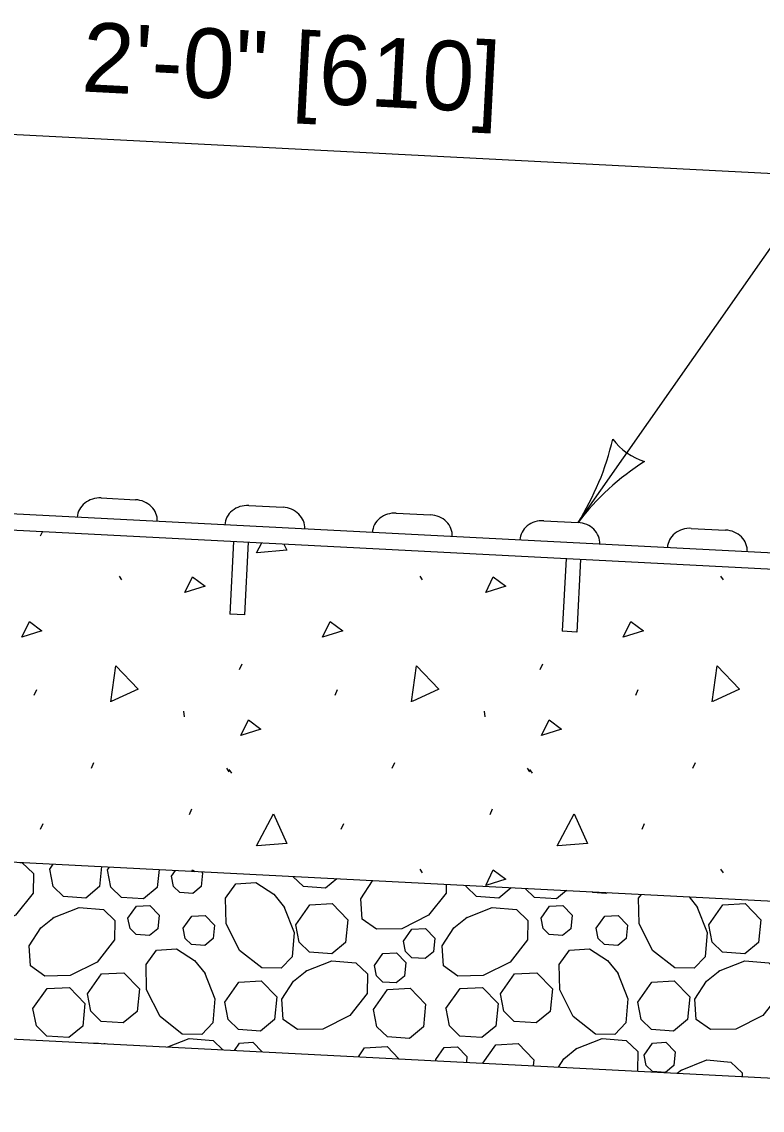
# Model space of a CAD drawing. Extents: x 49991.4 to 50021, y 49987.6 to 50011.4.
# Drawn here: x 50004.422 to 50005.061, y 50003.543 to 50004.482 of the extents above; entities that cross this region are included whole.
import ezdxf

# ---------------------------------------------------------------- set-up
doc = ezdxf.new("R2010")
doc.units = 0
for name, color, linetype in [('Level 1', 7, 'Continuous'), ('Level 2', 7, 'Continuous'), ('Level 3', 7, 'Continuous')]:
    doc.layers.add(name, color=color, linetype=linetype)

msp = doc.modelspace()

# ---------------------------------------------------------------- linework, layer by layer
at = {"layer": 'Level 1'}
for p, q in [((50005.6078, 50003.99629), (50003.78023, 50004.09047)), ((50005.60708, 50003.98226), (50003.7795, 50004.07644)), ((50004.49059, 50004.07152), (50004.52017, 50004.06999)), ((50004.6178, 50004.06496), (50004.64738, 50004.06344)), ((50004.74501, 50004.0584), (50004.77459, 50004.05688)), ((50004.87222, 50004.05185), (50004.9018, 50004.05032)), ((50004.99943, 50004.04529), (50005.02901, 50004.04377)), ((50004.60469, 50004.03391), (50004.60146, 50003.97124)), ((50004.61728, 50004.03326), (50004.61405, 50003.97059)), ((50004.89144, 50004.01914), (50004.88821, 50003.95646)), ((50004.90402, 50004.01849), (50004.90079, 50003.95581)), ((50004.61405, 50003.97059), (50004.60146, 50003.97124)), ((50004.90079, 50003.95581), (50004.88821, 50003.95646)), ((50002.75553, 50003.84288), (50005.60777, 50003.69589)), ((50002.72051, 50003.69208), (50005.60777, 50003.54329))]:
    msp.add_line(p, q, dxfattribs=at)
msp.add_lwpolyline([(50004.48395, 50003.6012), (50004.48808, 50003.60123), (50004.4883, 50003.60098)], dxfattribs=at)
for centre, major_axis, start_param, end_param in [((50004.48967, 50004.05391), (0.01967, -0.00101), 1.570424, 3.141593), ((50004.51927, 50004.05238), (-0.01967, 0.00101), 3.141593, 4.712762), ((50004.61688, 50004.04735), (0.01967, -0.00101), 1.570424, 3.141593), ((50004.64648, 50004.04583), (-0.01967, 0.00101), 3.141593, 4.712762), ((50004.74409, 50004.0408), (0.01967, -0.00101), 1.570424, 3.141593), ((50004.77369, 50004.03927), (-0.01967, 0.00101), 3.141593, 4.712762), ((50004.87131, 50004.03424), (0.01967, -0.00101), 1.570424, 3.141593), ((50004.9009, 50004.03272), (-0.01967, 0.00101), 3.141593, 4.712762), ((50004.99852, 50004.02769), (0.01967, -0.00101), 1.570424, 3.141593), ((50005.02811, 50004.02616), (-0.01967, 0.00101), 3.141593, 4.712762)]:
    msp.add_ellipse(centre, major_axis=major_axis, ratio=0.895257, start_param=start_param, end_param=end_param, dxfattribs=at)
at = {"layer": 'Level 2'}
for p, q in [((50004.43834, 50004.03878), (50004.43995, 50004.0424)), ((50004.62458, 50004.02417), (50004.62907, 50004.03266)), ((50004.50601, 50004.00414), (50004.50818, 50004.00089)), ((50004.76532, 50004.00414), (50004.76749, 50004.00089)), ((50005.02463, 50004.00414), (50005.0268, 50004.00089)), ((50004.60996, 50003.92348), (50004.61212, 50003.92835)), ((50004.86927, 50003.92348), (50004.87143, 50003.92835)), ((50004.43293, 50003.90128), (50004.4351, 50003.90616)), ((50004.69224, 50003.90128), (50004.69441, 50003.90616)), ((50004.95155, 50003.90128), (50004.95372, 50003.90616)), ((50004.56163, 50003.88769), (50004.56218, 50003.88282)), ((50004.82094, 50003.88769), (50004.82149, 50003.88282)), ((50004.48219, 50003.83849), (50004.48436, 50003.84336)), ((50004.7415, 50003.83849), (50004.74367, 50003.84336)), ((50005.00081, 50003.83849), (50005.00298, 50003.84336)), ((50004.59858, 50003.83849), (50004.60075, 50003.83524)), ((50004.60075, 50003.83726), (50004.60292, 50003.83401)), ((50004.85789, 50003.83849), (50004.86006, 50003.83524)), ((50004.86006, 50003.83726), (50004.86223, 50003.83401)), ((50004.56664, 50003.79836), (50004.56881, 50003.80323)), ((50004.82595, 50003.79836), (50004.82812, 50003.80323)), ((50004.43834, 50003.78591), (50004.44051, 50003.79078)), ((50004.69765, 50003.78591), (50004.69982, 50003.79078)), ((50004.95696, 50003.78591), (50004.95913, 50003.79078)), ((50004.44631, 50003.75132), (50004.44931, 50003.75559)), ((50004.49609, 50003.75058), (50004.49785, 50003.75309)), ((50004.55115, 50003.74527), (50004.55459, 50003.75017)), ((50004.76532, 50003.75127), (50004.76749, 50003.74802)), ((50005.02463, 50003.75127), (50005.0268, 50003.74802)), ((50004.9976, 50003.72734), (50005.00487, 50003.71823)), ((50004.77926, 50003.58599), (50004.77907, 50003.58694)), ((50004.9873, 50003.57526), (50004.99103, 50003.57824))]:
    msp.add_line(p, q, dxfattribs=at)
for points in [[(50004.64817, 50004.03167), (50004.65056, 50004.02633), (50004.62512, 50004.02417)], [(50004.56285, 50003.99006), (50004.56935, 50004.0036), (50004.58017, 50003.99548), (50004.56285, 50003.99006)], [(50004.82216, 50003.99006), (50004.82866, 50004.0036), (50004.83948, 50003.99548), (50004.82216, 50003.99006)], [(50004.42221, 50003.95137), (50004.42871, 50003.9649), (50004.43953, 50003.95678), (50004.42221, 50003.95137)], [(50004.68152, 50003.95137), (50004.68802, 50003.9649), (50004.69884, 50003.95678), (50004.68152, 50003.95137)], [(50004.94083, 50003.95137), (50004.94733, 50003.9649), (50004.95815, 50003.95678), (50004.94083, 50003.95137)], [(50004.49879, 50003.89568), (50004.50308, 50003.92662), (50004.52247, 50003.9066), (50004.4993, 50003.89587)], [(50004.7581, 50003.89568), (50004.76239, 50003.92662), (50004.78178, 50003.9066), (50004.75861, 50003.89587)], [(50005.01741, 50003.89568), (50005.0217, 50003.92662), (50005.04109, 50003.9066), (50005.01792, 50003.89587)], [(50004.61104, 50003.86664), (50004.61754, 50003.88017), (50004.62836, 50003.87205), (50004.61104, 50003.86664)], [(50004.87035, 50003.86664), (50004.87685, 50003.88017), (50004.88767, 50003.87205), (50004.87035, 50003.86664)], [(50004.62458, 50003.7713), (50004.63919, 50003.7989), (50004.65056, 50003.77346), (50004.62512, 50003.7713)], [(50004.88389, 50003.7713), (50004.8985, 50003.7989), (50004.90987, 50003.77346), (50004.88443, 50003.7713)], [(50004.42033, 50003.75708), (50004.42224, 50003.75692), (50004.43212, 50003.74752), (50004.43181, 50003.73065), (50004.41681, 50003.71148), (50004.39362, 50003.69989), (50004.37178, 50003.6995), (50004.35948, 50003.70824), (50004.35831, 50003.72564), (50004.3683, 50003.7412), (50004.37972, 50003.75032)], [(50004.49093, 50003.75345), (50004.48921, 50003.7362), (50004.47728, 50003.72627), (50004.45821, 50003.72765), (50004.44923, 50003.73635), (50004.44632, 50003.75131)], [(50004.54054, 50003.75089), (50004.539, 50003.73546), (50004.52706, 50003.72554), (50004.50798, 50003.72692), (50004.49901, 50003.73562), (50004.4961, 50003.75058)], [(50004.57699, 50003.74901), (50004.57806, 50003.7479), (50004.57689, 50003.7362), (50004.56973, 50003.73024), (50004.55829, 50003.73107), (50004.55289, 50003.73629), (50004.55115, 50003.74526)], [(50004.56873, 50003.74944), (50004.56935, 50003.75073), (50004.57124, 50003.74931)], [(50004.82216, 50003.73719), (50004.82866, 50003.75073), (50004.83948, 50003.74261), (50004.82216, 50003.73719)], [(50004.64811, 50003.71915), (50004.6571, 50003.69651), (50004.6553, 50003.67571), (50004.6459, 50003.66583), (50004.62903, 50003.66614), (50004.60985, 50003.68115), (50004.59826, 50003.70432), (50004.59788, 50003.72617), (50004.60662, 50003.73847), (50004.62402, 50003.73964), (50004.63958, 50003.72966), (50004.6487, 50003.71823)], [(50004.69385, 50003.74299), (50004.684, 50003.7348), (50004.66492, 50003.73618), (50004.65594, 50003.74489), (50004.65593, 50003.74494)], [(50004.78811, 50003.73813), (50004.78797, 50003.73065), (50004.77297, 50003.71148), (50004.74979, 50003.69989), (50004.72794, 50003.6995), (50004.71564, 50003.70824), (50004.71448, 50003.72564), (50004.72446, 50003.7412), (50004.7247, 50003.7414)], [(50004.84422, 50003.73524), (50004.83344, 50003.72627), (50004.81437, 50003.72765), (50004.8054, 50003.73635), (50004.80522, 50003.73725)], [(50004.89194, 50003.73278), (50004.88322, 50003.72554), (50004.86415, 50003.72692), (50004.85621, 50003.73462)], [(50004.92679, 50003.73098), (50004.9259, 50003.73024), (50004.91445, 50003.73107), (50004.91385, 50003.73165)], [(50005.00428, 50003.71915), (50005.01326, 50003.69651), (50005.01146, 50003.67571), (50005.00207, 50003.66583), (50004.98519, 50003.66614), (50004.96601, 50003.68115), (50004.95443, 50003.70432), (50004.95404, 50003.72617), (50004.95638, 50003.72946)], [(50004.6584, 50003.70322), (50004.67051, 50003.72043), (50004.68983, 50003.72153), (50004.70326, 50003.70761), (50004.70131, 50003.6881), (50004.68938, 50003.67817), (50004.6703, 50003.67955), (50004.66133, 50003.68825), (50004.65841, 50003.70322)], [(50005.01457, 50003.70322), (50005.02667, 50003.72043), (50005.046, 50003.72153), (50005.05942, 50003.70761), (50005.05748, 50003.6881), (50005.04555, 50003.67817), (50005.02647, 50003.67955), (50005.01749, 50003.68825), (50005.01458, 50003.70322)], [(50004.44903, 50003.70931), (50004.47168, 50003.71828), (50004.49247, 50003.71648), (50004.50236, 50003.70709), (50004.50204, 50003.69021), (50004.48704, 50003.67103), (50004.46386, 50003.65945), (50004.44201, 50003.65906), (50004.42971, 50003.6678), (50004.42855, 50003.68521), (50004.43852, 50003.70077), (50004.44995, 50003.70988)], [(50004.51369, 50003.70895), (50004.52095, 50003.71928), (50004.53255, 50003.71995), (50004.5406, 50003.71159), (50004.53944, 50003.69988), (50004.53228, 50003.69392), (50004.52083, 50003.69476), (50004.51545, 50003.69998), (50004.5137, 50003.70895)], [(50004.56135, 50003.70044), (50004.56862, 50003.71077), (50004.58021, 50003.71143), (50004.58827, 50003.70307), (50004.5871, 50003.69137), (50004.57995, 50003.68541), (50004.5685, 50003.68624), (50004.56311, 50003.69146), (50004.56136, 50003.70043)], [(50004.8052, 50003.70931), (50004.82784, 50003.71828), (50004.84863, 50003.71648), (50004.85853, 50003.70709), (50004.85821, 50003.69021), (50004.84321, 50003.67103), (50004.82002, 50003.65945), (50004.79818, 50003.65906), (50004.78588, 50003.6678), (50004.78472, 50003.68521), (50004.79469, 50003.70077), (50004.80612, 50003.70988)], [(50004.86986, 50003.70895), (50004.87712, 50003.71928), (50004.88871, 50003.71995), (50004.89677, 50003.71159), (50004.89561, 50003.69988), (50004.88844, 50003.69392), (50004.87699, 50003.69476), (50004.87161, 50003.69998), (50004.86987, 50003.70895)], [(50004.91752, 50003.70044), (50004.92478, 50003.71077), (50004.93638, 50003.71143), (50004.94444, 50003.70307), (50004.94327, 50003.69137), (50004.93611, 50003.68541), (50004.92467, 50003.68624), (50004.91928, 50003.69146), (50004.91753, 50003.70043)], [(50004.75126, 50003.68909), (50004.75853, 50003.69943), (50004.77012, 50003.70008), (50004.77817, 50003.69173), (50004.77701, 50003.68002), (50004.76985, 50003.67406), (50004.7584, 50003.67489), (50004.75302, 50003.68011), (50004.75127, 50003.68909)], [(50004.57964, 50003.66204), (50004.58862, 50003.63941), (50004.58682, 50003.61861), (50004.57743, 50003.60872), (50004.56055, 50003.60904), (50004.54137, 50003.62404), (50004.52979, 50003.64723), (50004.5294, 50003.66907), (50004.53814, 50003.68137), (50004.55555, 50003.68253), (50004.57111, 50003.67256), (50004.58023, 50003.66113)], [(50004.93581, 50003.66204), (50004.94479, 50003.63941), (50004.94299, 50003.61861), (50004.93359, 50003.60872), (50004.91672, 50003.60904), (50004.89754, 50003.62404), (50004.88596, 50003.64723), (50004.88557, 50003.66907), (50004.89431, 50003.68137), (50004.91172, 50003.68253), (50004.92728, 50003.67256), (50004.93639, 50003.66113)], [(50004.7263, 50003.6681), (50004.73356, 50003.67843), (50004.74515, 50003.67909), (50004.75321, 50003.67073), (50004.75205, 50003.65903), (50004.74488, 50003.65307), (50004.73343, 50003.6539), (50004.72805, 50003.65912), (50004.72631, 50003.6681)], [(50004.66686, 50003.66319), (50004.68951, 50003.67217), (50004.7103, 50003.67037), (50004.72018, 50003.66097), (50004.71986, 50003.64409), (50004.70486, 50003.62492), (50004.68168, 50003.61333), (50004.65983, 50003.61295), (50004.64754, 50003.62168), (50004.64637, 50003.63909), (50004.65635, 50003.65465), (50004.66778, 50003.66377)], [(50005.02303, 50003.66319), (50005.04567, 50003.67217), (50005.06646, 50003.67037), (50005.07634, 50003.66097), (50005.07603, 50003.64409), (50005.06103, 50003.62492), (50005.03785, 50003.61333), (50005.016, 50003.61295), (50005.00371, 50003.62168), (50005.00253, 50003.63909), (50005.01252, 50003.65465), (50005.02395, 50003.66377)], [(50004.47869, 50003.6436), (50004.49079, 50003.66082), (50004.51011, 50003.66192), (50004.52355, 50003.64799), (50004.5216, 50003.62848), (50004.50966, 50003.61855), (50004.49059, 50003.61994), (50004.48161, 50003.62864), (50004.4787, 50003.6436)], [(50004.59708, 50003.63665), (50004.60918, 50003.65387), (50004.6285, 50003.65497), (50004.64193, 50003.64104), (50004.63999, 50003.62153), (50004.62805, 50003.6116), (50004.60897, 50003.61298), (50004.6, 50003.62168), (50004.59709, 50003.63665)], [(50004.83486, 50003.6436), (50004.84695, 50003.66082), (50004.86627, 50003.66192), (50004.87971, 50003.64799), (50004.87777, 50003.62848), (50004.86582, 50003.61855), (50004.84675, 50003.61994), (50004.83778, 50003.62864), (50004.83486, 50003.6436)], [(50004.95324, 50003.63665), (50004.96535, 50003.65387), (50004.98467, 50003.65497), (50004.9981, 50003.64104), (50004.99615, 50003.62153), (50004.98422, 50003.6116), (50004.96514, 50003.61298), (50004.95617, 50003.62168), (50004.95326, 50003.63665)], [(50004.43175, 50003.63098), (50004.44386, 50003.64819), (50004.46318, 50003.6493), (50004.47661, 50003.63537), (50004.47467, 50003.61585), (50004.46273, 50003.60593), (50004.44365, 50003.60731), (50004.43468, 50003.61601), (50004.43177, 50003.63097)], [(50004.72549, 50003.63027), (50004.73759, 50003.64748), (50004.75692, 50003.64859), (50004.77034, 50003.63466), (50004.7684, 50003.61514), (50004.75647, 50003.60521), (50004.73739, 50003.6066), (50004.72841, 50003.6153), (50004.72551, 50003.63026)], [(50004.78792, 50003.63098), (50004.80003, 50003.64819), (50004.81935, 50003.6493), (50004.83278, 50003.63537), (50004.83083, 50003.61585), (50004.8189, 50003.60593), (50004.79982, 50003.60731), (50004.79085, 50003.61601), (50004.78794, 50003.63097)], [(50004.49297, 50003.60074), (50004.49398, 50003.6008), (50004.49409, 50003.60068)], [(50004.54796, 50003.5979), (50004.5664, 50003.60521), (50004.58719, 50003.60342), (50004.59558, 50003.59545)], [(50004.60543, 50003.59494), (50004.60986, 50003.60125), (50004.62145, 50003.6019), (50004.62935, 50003.59371)], [(50004.71237, 50003.58943), (50004.71775, 50003.59708), (50004.73706, 50003.59819), (50004.74724, 50003.58764)], [(50004.81973, 50003.5839), (50004.83082, 50003.5997), (50004.85015, 50003.6008), (50004.86357, 50003.58687), (50004.86306, 50003.58167)], [(50004.89993, 50003.59624), (50004.92257, 50003.60521), (50004.94336, 50003.60342), (50004.95324, 50003.59403), (50004.95294, 50003.57715), (50004.95285, 50003.57704)], [(50004.95876, 50003.59091), (50004.96602, 50003.60125), (50004.97761, 50003.6019), (50004.98567, 50003.59355), (50004.98451, 50003.58184), (50004.97734, 50003.57588), (50004.9659, 50003.57671), (50004.96051, 50003.58194), (50004.95877, 50003.59091)], [(50004.77906, 50003.58694), (50004.78633, 50003.59727), (50004.79792, 50003.59793), (50004.80598, 50003.58957), (50004.80549, 50003.58463)], [(50004.88482, 50003.58055), (50004.88941, 50003.58771), (50004.90084, 50003.59683)], [(50004.99011, 50003.57766), (50005.01275, 50003.58663), (50005.03355, 50003.58484), (50005.04343, 50003.57544), (50005.04337, 50003.57237)]]:
    msp.add_lwpolyline(points, dxfattribs=at)
at = {"layer": 'Level 3'}
for p, q in [((50003.79742, 50004.41704), (50005.11117, 50004.34933)), ((50004.9018, 50004.05032), (50005.08823, 50004.31657))]:
    msp.add_line(p, q, dxfattribs=at)
for centre, radius, start, end in [((50004.70458, 50004.17439), 0.233, 327.82731, 347.07716), ((50004.97534, 50004.15535), 0.05477, 217.13882, 252.86118), ((50005.07851, 50003.91541), 0.22232, 122.45601, 142.63952)]:
    msp.add_arc(centre, radius, start, end, dxfattribs=at)

# ---------------------------------------------------------------- texts
at = {"layer": 'Level 2'}
msp.add_text('2\'-0" [610]', height=0.06, rotation=357.05, dxfattribs=at).set_placement((50004.47298, 50004.42228))

doc.saveas('drawing.dxf')
